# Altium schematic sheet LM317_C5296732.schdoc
size 127 x 101 mm
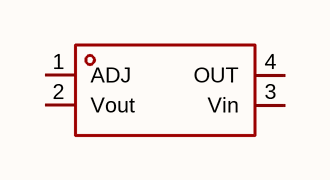
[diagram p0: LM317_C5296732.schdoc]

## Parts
U?  lm317_c5296732  [SOT-223-4_L6.5-W3.5-P2.30-LS7.0-BR]  (value not drawn)

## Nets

Not connected (* = marked no-connect by the designer): U? 1(ADJ) 2(Vout) 3(Vin) 4(OUT)

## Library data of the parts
U? = lm317_c5296732: 输出极性:正极;工作电压:40V;输出电压:1.3V~37V;输出电流:1A;电源纹波抑制比(PSRR):80dB@(120Hz);输出类型:可调;; Manufacturer: JSMSEMI(杰盛微); ManufacturerPart: LM317; AddInBom: yes; ModelId: 925194bf9823436183a3e0b978a8d076; ModelName: SOT-223-4P_L6.5-W3.5-H1.6-LS7.0-P2.30; ModelTransform: 279.89794,255.905,0,180,0,0,-0.0005,-0.0005,0; Output Configuration: 正极; Voltage - Supply: 40V; Output Current: 1A; Noise: 0.003%Vout; Output Type: 可调; Number of Outputs: 1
